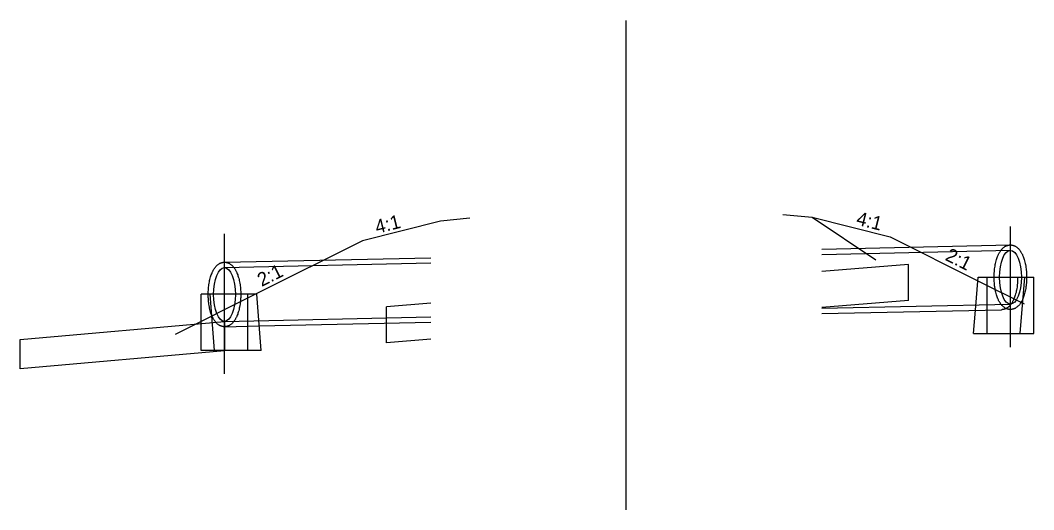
# Model space of a CAD drawing. Extents: x -366 to 568, y 606 to 841.
# Drawn here: x -366 to -262.3, y 679.8 to 729.8 of the extents above; entities that cross this region are included whole.
import ezdxf

# ---------------------------------------------------------------- set-up
doc = ezdxf.new("R2010")
doc.units = 0
for name, color, linetype in [('RD_X_Fence', 7, 'Continuous'), ('RD_X_GR_Lt', 7, 'Continuous'), ('RW_X_Text', 7, 'Continuous'), ('SH_Major_Grid_Line', 7, 'Continuous'), ('SH_Text', 7, 'Continuous'), ('UT_X_Telecom', 7, 'Continuous'), ('XS_P_Pavt_Surface', 7, 'Continuous')]:
    doc.layers.add(name, color=color, linetype=linetype)

msp = doc.modelspace()

# ---------------------------------------------------------------- linework, layer by layer
at = {"layer": 'RD_X_Fence'}
msp.add_lwpolyline([(-366.01, 697.14), (-345.12, 698.99), (-345.12, 695.99), (-366.01, 694.14)], close=True, dxfattribs=at)
at = {"layer": 'RD_X_GR_Lt'}
for p, q in [((-275.14, 704.8), (-284.01, 704.08)), ((-275.14, 701.13), (-275.14, 704.8)), ((-324.01, 700.85), (-328.56, 700.48)), ((-275.14, 701.13), (-284.01, 700.42)), ((-328.56, 696.81), (-328.56, 700.48)), ((-324.01, 697.18), (-328.56, 696.81))]:
    msp.add_line(p, q, dxfattribs=at)
at = {"layer": 'RW_X_Text'}
for p, q in [((-284.01, 706.38), (-264.72, 706.8)), ((-284.01, 705.83), (-264.72, 706.26)), ((-345.12, 705.04), (-324.01, 705.5)), ((-345.12, 704.5), (-324.01, 704.96)), ((-284.01, 700.33), (-264.72, 700.75)), ((-284.01, 699.79), (-265.64, 700.19)), ((-345.12, 698.99), (-324.01, 699.46)), ((-341.56, 698.54), (-324.01, 698.92)), ((-345.12, 698.45), (-341.56, 698.54))]:
    msp.add_line(p, q, dxfattribs=at)
for centre, major_axis in [((-264.72, 703.5), (0, 2.75)), ((-345.12, 701.74), (0, -2.75))]:
    msp.add_ellipse(centre, major_axis=major_axis, ratio=0.406586, dxfattribs=at)
for points in [[(-263.06, 703.5), (-263.06, 703.31), (-263.07, 703.11), (-263.1, 702.73), (-263.12, 702.54), (-263.19, 702.18), (-263.22, 702), (-263.32, 701.67), (-263.37, 701.51), (-263.46, 701.28), (-263.49, 701.21), (-263.56, 701.06), (-263.6, 701), (-263.68, 700.87), (-263.72, 700.81), (-263.81, 700.69), (-263.86, 700.63), (-263.96, 700.53), (-264.01, 700.48), (-264.13, 700.39), (-264.2, 700.35), (-264.3, 700.3), (-264.34, 700.29), (-264.41, 700.26), (-264.45, 700.25), (-264.52, 700.23), (-264.56, 700.22), (-264.64, 700.21), (-264.68, 700.21), (-264.72, 700.21), (-264.77, 700.21), (-264.81, 700.21), (-264.89, 700.22), (-264.93, 700.23), (-265, 700.25), (-265.04, 700.26), (-265.11, 700.29), (-265.15, 700.3), (-265.25, 700.35), (-265.32, 700.39), (-265.43, 700.48), (-265.49, 700.53), (-265.59, 700.63), (-265.64, 700.69), (-265.73, 700.81), (-265.77, 700.87), (-265.85, 701), (-265.89, 701.06), (-265.96, 701.21), (-265.99, 701.28), (-266.08, 701.51), (-266.13, 701.67), (-266.23, 702), (-266.26, 702.18), (-266.32, 702.54), (-266.35, 702.73), (-266.38, 703.11), (-266.39, 703.31), (-266.39, 703.7), (-266.38, 703.9), (-266.35, 704.28), (-266.32, 704.47), (-266.26, 704.83), (-266.23, 705), (-266.13, 705.34), (-266.08, 705.5), (-265.99, 705.73), (-265.96, 705.8), (-265.89, 705.94), (-265.85, 706.01), (-265.77, 706.14), (-265.73, 706.2), (-265.64, 706.32), (-265.59, 706.37), (-265.49, 706.48), (-265.43, 706.53), (-265.32, 706.62), (-265.25, 706.66), (-265.15, 706.71), (-265.11, 706.72), (-265.04, 706.75), (-265, 706.76), (-264.93, 706.78), (-264.89, 706.79), (-264.81, 706.8), (-264.77, 706.8), (-264.72, 706.8)], [(-264.72, 706.8), (-264.68, 706.8), (-264.64, 706.8), (-264.56, 706.79), (-264.52, 706.78), (-264.45, 706.76), (-264.41, 706.75), (-264.34, 706.72), (-264.3, 706.71), (-264.2, 706.66), (-264.13, 706.62), (-264.01, 706.53), (-263.96, 706.48), (-263.86, 706.37), (-263.81, 706.32), (-263.72, 706.2), (-263.68, 706.14), (-263.6, 706.01), (-263.56, 705.94), (-263.49, 705.8), (-263.46, 705.73), (-263.37, 705.5), (-263.32, 705.34), (-263.22, 705), (-263.19, 704.83), (-263.12, 704.47), (-263.1, 704.28), (-263.07, 703.9), (-263.06, 703.7), (-263.06, 703.5), (-263.06, 703.5), (-263.06, 703.5)], [(-345.12, 698.45), (-345.08, 698.45), (-345.04, 698.45), (-344.96, 698.46), (-344.92, 698.47), (-344.84, 698.49), (-344.8, 698.5), (-344.73, 698.53), (-344.69, 698.54), (-344.59, 698.59), (-344.53, 698.63), (-344.41, 698.72), (-344.35, 698.77), (-344.25, 698.88), (-344.2, 698.93), (-344.11, 699.05), (-344.07, 699.11), (-343.99, 699.24), (-343.96, 699.31), (-343.89, 699.45), (-343.85, 699.52), (-343.76, 699.75), (-343.71, 699.91), (-343.62, 700.25), (-343.58, 700.42), (-343.52, 700.78), (-343.49, 700.97), (-343.46, 701.35), (-343.45, 701.55), (-343.45, 701.94), (-343.46, 702.14), (-343.49, 702.52), (-343.52, 702.71), (-343.58, 703.07), (-343.62, 703.24), (-343.71, 703.58), (-343.76, 703.74), (-343.85, 703.97), (-343.89, 704.04), (-343.96, 704.18), (-343.99, 704.25), (-344.07, 704.38), (-344.11, 704.44), (-344.2, 704.56), (-344.25, 704.61), (-344.35, 704.72), (-344.41, 704.77), (-344.53, 704.86), (-344.59, 704.9), (-344.69, 704.95), (-344.73, 704.96), (-344.8, 704.99), (-344.84, 705), (-344.92, 705.02), (-344.96, 705.03), (-345.04, 705.04), (-345.08, 705.04), (-345.16, 705.04), (-345.2, 705.04), (-345.28, 705.03), (-345.32, 705.02), (-345.39, 705), (-345.43, 704.99), (-345.51, 704.96), (-345.54, 704.95), (-345.64, 704.9), (-345.71, 704.86), (-345.83, 704.77), (-345.88, 704.72), (-345.98, 704.61), (-346.03, 704.56), (-346.12, 704.44), (-346.16, 704.38), (-346.24, 704.25), (-346.28, 704.18), (-346.35, 704.04), (-346.38, 703.97), (-346.47, 703.74), (-346.53, 703.58), (-346.62, 703.24), (-346.66, 703.07), (-346.72, 702.71), (-346.74, 702.52), (-346.77, 702.14), (-346.78, 701.94), (-346.78, 701.55), (-346.77, 701.35), (-346.74, 700.97), (-346.72, 700.78), (-346.66, 700.42), (-346.62, 700.25), (-346.53, 699.91), (-346.47, 699.75), (-346.38, 699.52), (-346.35, 699.45), (-346.28, 699.31), (-346.24, 699.24), (-346.16, 699.11), (-346.12, 699.05), (-346.03, 698.93), (-345.98, 698.88), (-345.88, 698.77), (-345.83, 698.72), (-345.71, 698.63), (-345.64, 698.59), (-345.54, 698.54), (-345.51, 698.53), (-345.43, 698.5), (-345.39, 698.49), (-345.32, 698.47), (-345.28, 698.46), (-345.2, 698.45), (-345.16, 698.45), (-345.12, 698.45)]]:
    msp.add_open_spline(points, degree=3, dxfattribs=at)
at = {"layer": 'SH_Major_Grid_Line'}
for p, q in [((-304.01, 679.75), (-304.01, 729.75)), ((-304.01, 679.75), (-304.01, 729.75)), ((-264.72, 700.81), (-264.72, 708.68)), ((-345.12, 693.62), (-345.12, 707.93)), ((-264.72, 696.37), (-264.72, 700.75))]:
    msp.add_line(p, q, dxfattribs=at)
at = {"layer": 'UT_X_Telecom'}
for p, q in [((-268.3, 700.13), (-268.03, 703.5)), ((-268.03, 703.5), (-267.11, 703.5)), ((-267.11, 697.75), (-267.11, 703.5)), ((-267.11, 703.5), (-266.39, 703.5)), ((-266.39, 703.5), (-263.98, 703.5)), ((-263.98, 703.5), (-263.25, 703.5)), ((-263.71, 697.75), (-263.25, 703.5)), ((-263.25, 703.5), (-262.34, 703.5)), ((-262.34, 697.75), (-262.34, 703.5)), ((-347.51, 696.02), (-347.51, 701.77)), ((-346.78, 701.77), (-347.51, 701.77)), ((-343.45, 701.77), (-346.78, 701.77)), ((-346.14, 696.02), (-346.59, 701.77)), ((-342.73, 701.77), (-343.45, 701.77)), ((-342.73, 696.02), (-342.73, 701.77)), ((-341.81, 701.77), (-342.73, 701.77)), ((-341.36, 696.02), (-341.81, 701.77)), ((-268.48, 697.75), (-268.3, 700.13)), ((-268.48, 697.75), (-262.34, 697.75)), ((-342.73, 696.02), (-347.51, 696.02)), ((-341.36, 696.02), (-342.73, 696.02))]:
    msp.add_line(p, q, dxfattribs=at)
msp.add_open_spline([(-263.98, 703.5), (-263.98, 703.29), (-263.98, 703.09), (-264.02, 702.71), (-264.04, 702.52), (-264.1, 702.16), (-264.14, 701.98), (-264.23, 701.65), (-264.28, 701.49), (-264.38, 701.26), (-264.41, 701.19), (-264.48, 701.04), (-264.51, 700.98), (-264.59, 700.85), (-264.63, 700.79), (-264.72, 700.67), (-264.77, 700.61), (-264.87, 700.51), (-264.93, 700.46), (-265.05, 700.37), (-265.11, 700.33), (-265.21, 700.28), (-265.25, 700.27), (-265.32, 700.24), (-265.36, 700.23), (-265.44, 700.21), (-265.48, 700.2), (-265.56, 700.19), (-265.6, 700.19), (-265.64, 700.19)], degree=3, dxfattribs=at)
at = {"layer": 'XS_P_Pavt_Surface'}
for p, q in [((-323.01, 709.24), (-331.01, 707.24)), ((-320.01, 709.54), (-323.01, 709.24)), ((-288.01, 709.93), (-285.01, 709.63)), ((-285.01, 709.63), (-277.01, 707.63)), ((-285.01, 709.63), (-278.48, 705.28)), ((-331.01, 707.24), (-341.96, 701.77)), ((-277.01, 707.63), (-268.05, 703.15)), ((-268.05, 703.15), (-263.32, 700.78)), ((-341.96, 701.77), (-350.17, 697.66))]:
    msp.add_line(p, q, dxfattribs=at)

# ---------------------------------------------------------------- texts
at = {"layer": 'SH_Text'}
for s, rotation, p in [('4:1', 14.0362, (-329.52, 707.94)), ('4:1', 345.9638, (-280.57, 708.89)), ('2:1', 333.4349, (-271.49, 705.3)), ('2:1', 26.5651, (-341.31, 702.5))]:
    msp.add_text(s, height=1.4, rotation=rotation, dxfattribs=at).set_placement(p)

doc.saveas('drawing.dxf')
